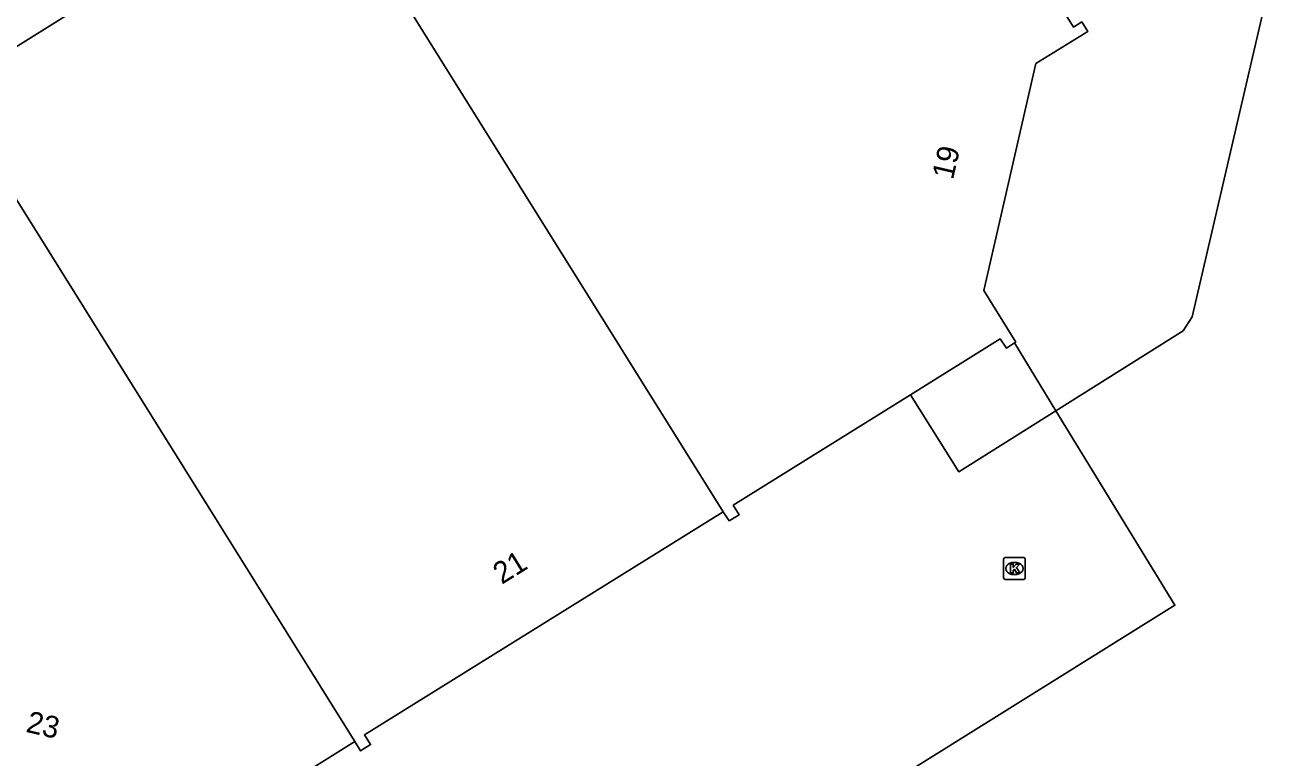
# Model space of a CAD drawing. Extents: x 158461 to 159795, y 387220 to 388672.
# Drawn here: x 158607.5 to 158665.1, y 387671.3 to 387705 of the extents above; entities that cross this region are included whole.
import ezdxf

# ---------------------------------------------------------------- set-up
doc = ezdxf.new("R2010")
doc.units = 0
for name, color, linetype in [('IMGEO_Hek', 7, 'Continuous'), ('IMGEO_Kolk', 7, 'Continuous'), ('IMGEO_Pand', 7, 'Continuous'), ('IMGEO_Pand_nummerreeks', 7, 'Continuous'), ('IMGEO_Rijbaan_lokaal_open', 7, 'Continuous'), ('IMGEO_Voetpad_open', 7, 'Continuous')]:
    doc.layers.add(name, color=color, linetype=linetype)

msp = doc.modelspace()

# ---------------------------------------------------------------- linework, layer by layer
at = {"layer": 'IMGEO_Hek'}
for points in [[(158653.031, 387690.361), (158654.938, 387687.24)], [(158654.938, 387687.24), (158660.413, 387678.284)], [(158660.413, 387678.284), (158600.856, 387641.123)]]:
    msp.add_lwpolyline(points, dxfattribs=at)
at = {"layer": 'IMGEO_Kolk'}
for p, q in [((158652.528, 387679.551), (158652.528, 387680.403)), ((158652.603, 387680.477), (158653.455, 387680.477)), ((158653.016, 387680.257), (158653.041, 387680.257)), ((158653.529, 387680.403), (158653.529, 387679.551)), ((158653.039, 387679.697), (158653.014, 387679.697)), ((158653.455, 387679.477), (158652.603, 387679.477))]:
    msp.add_line(p, q, dxfattribs=at)
for points in [[(158652.528, 387679.551), (158652.528, 387680.403)], [(158652.603, 387680.477), (158653.455, 387680.477)], [(158652.849, 387680.177), (158652.972, 387680.177), (158652.972, 387680.026), (158653.102, 387680.177), (158653.266, 387680.177), (158653.12, 387680.026), (158653.273, 387679.777), (158653.121, 387679.777), (158653.036, 387679.941), (158652.972, 387679.874), (158652.972, 387679.777), (158652.849, 387679.777), (158652.849, 387680.177)], [(158653.529, 387680.403), (158653.529, 387679.551)], [(158653.455, 387679.477), (158652.603, 387679.477)]]:
    msp.add_lwpolyline(points, dxfattribs=at)
for centre, start, end in [((158652.605, 387680.401), 91.55205, 178.44795), ((158652.605, 387680.401), 91.55205, 178.44795), ((158653.453, 387680.401), 1.55205, 88.44795), ((158653.453, 387680.401), 1.55205, 88.44795), ((158652.605, 387679.553), 181.55205, 268.44795), ((158652.605, 387679.553), 181.55205, 268.44795), ((158653.453, 387679.553), 271.55205, 358.44795), ((158653.453, 387679.553), 271.55205, 358.44795)]:
    msp.add_arc(centre, 0.0765, start, end, dxfattribs=at)
for centre, major_axis, ratio, start_param, end_param in [((158653.015, 387679.977), (-0.387, 0.002), 0.722429, 4.712389, 7.853982), ((158653.04, 387679.977), (-0.39, 0.002), 0.717154, 1.570796, 4.712389)]:
    msp.add_ellipse(centre, major_axis=major_axis, ratio=ratio, start_param=start_param, end_param=end_param, dxfattribs=at)
at = {"layer": 'IMGEO_Pand'}
for points in [[(158653.031, 387690.361), (158653.092, 387690.4), (158651.615, 387692.771), (158654.02, 387703.221), (158656.401, 387704.693), (158656.124, 387705.139), (158655.749, 387704.906), (158642.493, 387726.138), (158635.284, 387721.635)], [(158620.864, 387712.627), (158603.909, 387702.036)], [(158639.621, 387682.593), (158620.864, 387712.627)], [(158622.665, 387672.006), (158603.909, 387702.036)], [(158648.248, 387687.974), (158652.373, 387690.544), (158652.663, 387690.129), (158653.031, 387690.361)], [(158648.248, 387687.974), (158640.085, 387682.889), (158640.353, 387682.45), (158639.892, 387682.174), (158639.621, 387682.593)], [(158591.75, 387683.827), (158600.23, 387670.246), (158599.884, 387670.019), (158600.169, 387669.557), (158602.479, 387671.028), (158612.964, 387668.614), (158614.421, 387666.241), (158614.88, 387666.528), (158614.613, 387666.97), (158622.665, 387672.006)], [(158622.665, 387672.006), (158622.93, 387671.582), (158623.387, 387671.867), (158623.107, 387672.325), (158639.621, 387682.593)]]:
    msp.add_lwpolyline(points, dxfattribs=at)
at = {"layer": 'IMGEO_Rijbaan_lokaal_open'}
for points in [[(158654.938, 387687.24), (158650.472, 387684.434), (158648.248, 387687.974)], [(158654.938, 387687.24), (158660.413, 387678.284), (158600.856, 387641.123)]]:
    msp.add_lwpolyline(points, dxfattribs=at)
at = {"layer": 'IMGEO_Voetpad_open'}
for points in [[(158663.087, 387712.133), (158664.963, 387709.124), (158665.114, 387708.357), (158661.211, 387691.563), (158660.796, 387690.921), (158654.938, 387687.24)], [(158653.031, 387690.361), (158654.938, 387687.24)]]:
    msp.add_lwpolyline(points, dxfattribs=at)

# ---------------------------------------------------------------- texts
at = {"layer": 'IMGEO_Pand_nummerreeks'}
for s, rotation, p in [('19', 77.03942, (158650.196, 387697.844)), ('21', 31.87364, (158629.428, 387679.222)), ('23', 347.03397, (158607.481, 387672.462))]:
    msp.add_text(s, height=1, rotation=rotation, dxfattribs=at).set_placement(p)

doc.saveas('drawing.dxf')
